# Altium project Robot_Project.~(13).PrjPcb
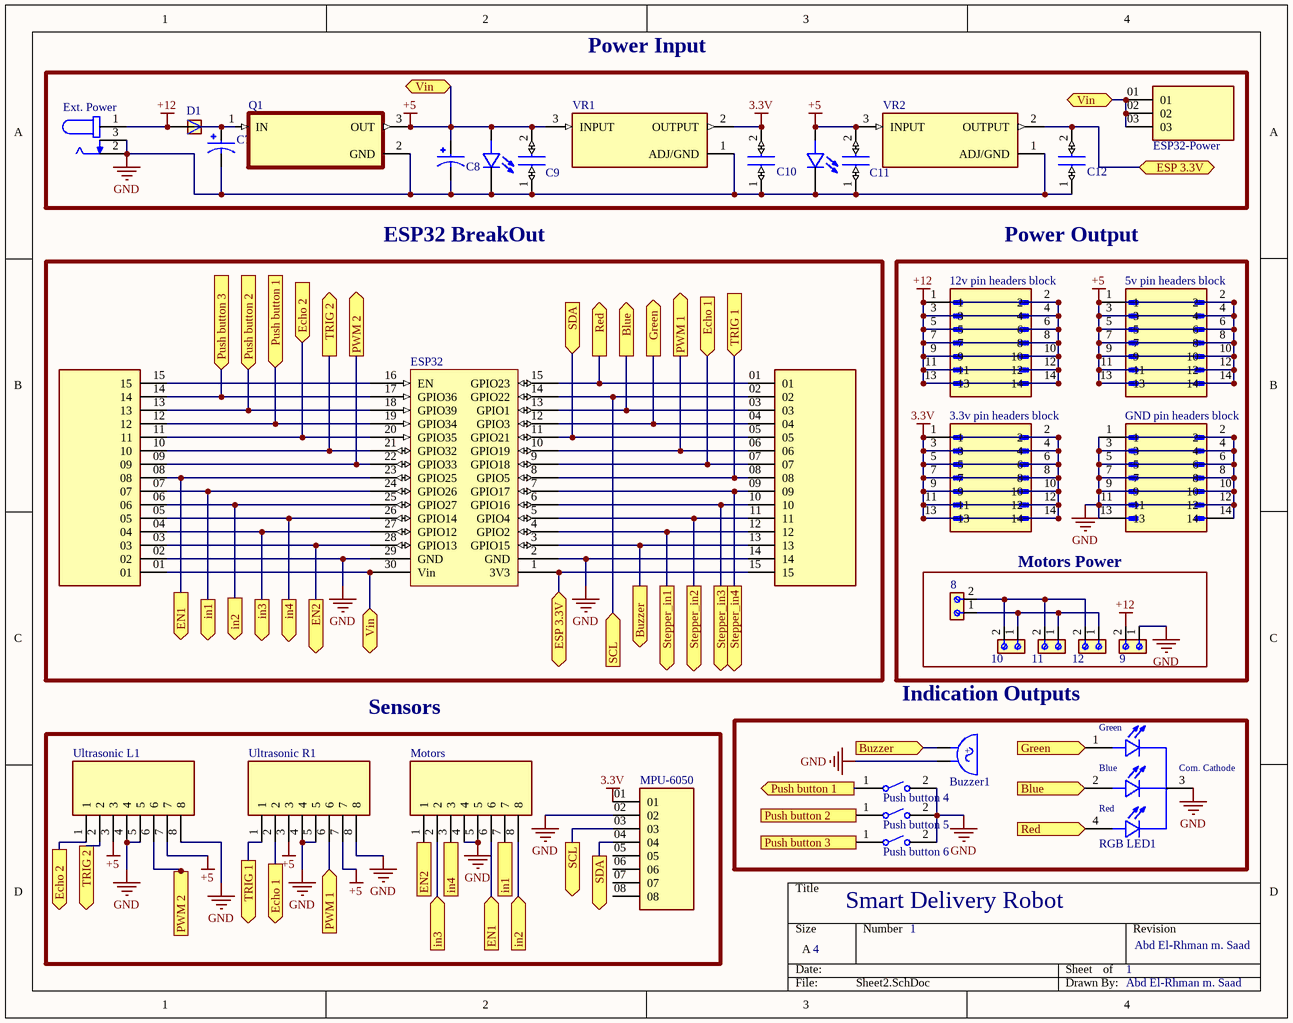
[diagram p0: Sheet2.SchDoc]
1 sheet, 35 parts. Net scope: flat (ports and power ports of the same name join across sheets).
Board files: PCB1.PcbDoc, PCB2.PcbDoc

## Sheet Sheet2.SchDoc: Smart Delivery Robot
size A; Date: 27/12/2023; DrawnBy: Abd El-Rhman m. Saad; Engineer: Abd El-Rhman m. Saad; SheetNumber: 2; SheetTotal: 2

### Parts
1  LED 5mm  [LED 5mm]  (value not drawn)
2  LED 5mm  [LED 5mm]  (value not drawn)
3.3v_pin_headers_block  3.3v pin headers block  [AMPHENOL_52601-S14-4LF]  (value not drawn)
5v_pin_headers_block  5v pin headers block  [AMPHENOL_52601-S14-4LF]  (value not drawn)
8  From Buck  [691213510002]  (value not drawn)
9  From Buck  [691213510002]  (value not drawn)
10  From Buck  [691213510002]  (value not drawn)
11  From Buck  [691213510002]  (value not drawn)
12  From Buck  [691213510002]  (value not drawn)
12v_pin_headers_block  12v pin headers block  [AMPHENOL_52601-S14-4LF]  (value not drawn)
Buzzer1  Buzzer  [Buzzer 5V]  (value not drawn)
C7  CAP  33UF 50V RADIAL  [CAP  33UF 50V RADIAL]  (value not drawn)
C8  CAP  33UF 50V RADIAL  [CAP  33UF 50V RADIAL]  (value not drawn)
C9  Ceramic Capacitor 100nF  [C320C]  (value not drawn)
C10  Ceramic Capacitor 100nF  [C320C]  (value not drawn)
C11  Ceramic Capacitor 100nF  [C320C]  (value not drawn)
C12  Ceramic Capacitor 100nF  [C320C]  (value not drawn)
D1  RL207  [DIOAD1300W80L670D310]  (value not drawn)
ESP32  ESP32DEVKITV1  [ESP32DEVKITV1]  (value not drawn)
ESP32-Power  TS-103-T-A-1  [SAMTEC_TS-103-T-A-1]  (value not drawn)
Ext._Power  DC Power Jack Female Socket  [DC Power Jack Female Socket]  (value not drawn)
GND_pin_headers_block  GND pin headers block  [AMPHENOL_52601-S14-4LF]  (value not drawn)
J1  TS-115-T-A-1  [SAMTEC_TS-115-T-A-1]  (value not drawn)
J2  TS-115-T-A-1  [SAMTEC_TS-115-T-A-1]  (value not drawn)
Motors  Pin header female block 8 pin  [Pin header female block 8 pin]  (value not drawn)
MPU-6050  MPU-6050  [MPU-6050]  (value not drawn)
Push_button_4  FSM8JRT  [TE_FSM8JRT]  (value not drawn)
Push_button_5  FSM8JRT  [TE_FSM8JRT]  (value not drawn)
Push_button_6  FSM8JRT  [TE_FSM8JRT]  (value not drawn)
Q1  LM7805CT  [TO254P1054X470X1955-3]  (value not drawn)
RGB_LED1  common cathode  [LED RGB 5mm]  (value not drawn)
Ultrasonic_L1  Pin header female block 8 pin  [Pin header female block 8 pin]  (value not drawn)
Ultrasonic_R1  Pin header female block 8 pin  [Pin header female block 8 pin]  (value not drawn)
VR1  LM1117T-3.3  [TO254P1054X470X1955-3]  (value not drawn)
VR2  LM1117T-3.3  [TO254P1054X470X1955-3]  (value not drawn)

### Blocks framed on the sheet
Power Input: 1 2 C7-C12 D1 ESP32-Power Ext._Power Q1 VR1 VR2
ESP32 BreakOut: ESP32 J1 J2
Power Output: 3.3v_pin_headers_block 5v_pin_headers_block 12v_pin_headers_block GND_pin_headers_block
Motors Power: 8-12
Indication Outputs: Buzzer1 Push_button_4-Push_button_6 RGB_LED1
Sensors: Motors MPU-6050 Ultrasonic_L1 Ultrasonic_R1

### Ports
Blue (in, see Sheet1[2B], Sheet1[4B], Sheet2[2B]), Blue (out, see Sheet1[2B], Sheet1[4B], Sheet2[4D]), Buzzer (in, see Sheet1[2C], Sheet1[4A], Sheet2[2C]), Buzzer (out, see Sheet1[2C], Sheet1[4A], Sheet2[3C]), Echo 1 (in, see Sheet1[3B], Sheet1[4B], Sheet2[1D]), Echo 1 (out, see Sheet1[3B], Sheet1[4B], Sheet2[3B]), Echo 2 (in, see Sheet1[1B], Sheet1[3B], Sheet2[1D]), Echo 2 (out, see Sheet1[1B], Sheet1[3B], Sheet2[1B]), EN1 (in, see Sheet1[1C], Sheet1[4C], Sheet2[1C]), EN1 (out, see Sheet1[1C], Sheet1[4C], Sheet2[2D]), EN2 (in, see Sheet1[2C], Sheet1[4C], Sheet2[1C]), EN2 (out, see Sheet1[2C], Sheet1[4C], Sheet2[2D]), ESP 3.3V (bidir, see Sheet1[2C], Sheet1[3A], Sheet2[2C]), ESP 3.3V (bidir, see Sheet1[2C], Sheet1[3A], Sheet2[4A]), Green (in, see Sheet1[3B], Sheet1[4B], Sheet2[3B]), Green (out, see Sheet1[3B], Sheet1[4B], Sheet2[4C]), in1 (in, see Sheet1[1C], Sheet1[4C], Sheet2[1C]), in1 (out, see Sheet1[1C], Sheet1[4C], Sheet2[2D]), in2 (in, see Sheet1[1C], Sheet1[4C], Sheet2[1C]), in2 (out, see Sheet1[1C], Sheet1[4C], Sheet2[2D]), in3 (in, see Sheet1[1C], Sheet1[4C], Sheet2[1C]), in3 (out, see Sheet1[1C], Sheet1[4C], Sheet2[2D]), in4 (in, see Sheet1[1C], Sheet1[4C], Sheet2[1C]), in4 (out, see Sheet1[1C], Sheet1[4C], Sheet2[2D]), Push button 1 (in, see Sheet1[1B], Sheet1[4C], Sheet2[3D]), Push button 1 (out, see Sheet1[1B], Sheet1[4C], Sheet2[1B]), Push button 2 (in, see Sheet1[1B], Sheet1[4D], Sheet2[3D]), Push button 2 (out, see Sheet1[1B], Sheet1[4D], Sheet2[1B]), Push button 3 (in, see Sheet1[1B], Sheet1[4D], Sheet2[3D]), Push button 3 (out, see Sheet1[1B], Sheet1[4D], Sheet2[1B]), PWM 1 (in, see Sheet1[3B], Sheet1[4B], Sheet2[3B]), PWM 1 (out, see Sheet1[3B], Sheet1[4B], Sheet2[2D]), PWM 2 (in, see Sheet1[2B], Sheet1[4B], Sheet2[2B]), PWM 2 (out, see Sheet1[2B], Sheet1[4B], Sheet2[1D]), Red (in, see Sheet1[2B], Sheet1[4B], Sheet2[2B]), Red (out, see Sheet1[2B], Sheet1[4B], Sheet2[4D]), SCL (in, see Sheet1[2C], Sheet1[3C], Sheet2[2D]), SCL (out, see Sheet1[2C], Sheet1[3C], Sheet2[2C]), SDA (in, see Sheet1[2B], Sheet1[4C], Sheet2[2D]), SDA (out, see Sheet1[2B], Sheet1[4C], Sheet2[2B]), Stepper_in1 (out, see Sheet1[2C]), Stepper_in2 (out, see Sheet1[3C]), Stepper_in3 (out, see Sheet1[3C]), Stepper_in4 (out, see Sheet1[3C]), TRIG 1 (in, see Sheet1[3B], Sheet1[4B], Sheet2[1D]), TRIG 1 (out, see Sheet1[3B], Sheet1[4B], Sheet2[3B]), TRIG 2 (out, see Sheet1[1B], Sheet1[3B], Sheet2[1D]), TRIG 2 (out, see Sheet1[1B], Sheet1[3B], Sheet2[2B]), Vin (bidir, see Sheet1[2A], Sheet1[2C], Sheet2[2A], Sheet2[2C]), Vin (bidir, see Sheet1[2A], Sheet1[2C], Sheet2[2A], Sheet2[4A]), Vin (bidir, see Sheet1[2A], Sheet1[2C], Sheet2[2C], Sheet2[4A])

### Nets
3.3V: 3.3v_pin_headers_block.1 3.3v_pin_headers_block.2 3.3v_pin_headers_block.3 3.3v_pin_headers_block.4 3.3v_pin_headers_block.5 3.3v_pin_headers_block.6 3.3v_pin_headers_block.7 3.3v_pin_headers_block.8 3.3v_pin_headers_block.9 3.3v_pin_headers_block.10 3.3v_pin_headers_block.11 3.3v_pin_headers_block.12 3.3v_pin_headers_block.13 3.3v_pin_headers_block.14 C10.2 MPU-6050.01 VR1.2(OUTPUT)
+5: 1.A 2.A 5v_pin_headers_block.1 5v_pin_headers_block.2 5v_pin_headers_block.3 5v_pin_headers_block.4 5v_pin_headers_block.5 5v_pin_headers_block.6 5v_pin_headers_block.7 5v_pin_headers_block.8 5v_pin_headers_block.9 5v_pin_headers_block.10 5v_pin_headers_block.11 5v_pin_headers_block.12 5v_pin_headers_block.13 5v_pin_headers_block.14 C8.P C9.2 C11.2 ESP32.30(Vin) ESP32-Power.01 ESP32-Power.02 ESP32-Power.03 J2.01 Q1.3(OUT) Ultrasonic_L1.3 Ultrasonic_L1.7 Ultrasonic_R1.3 Ultrasonic_R1.7 VR1.3(INPUT) VR2.3(INPUT) ; port Vin
+12: 9.2 12v_pin_headers_block.1 12v_pin_headers_block.2 12v_pin_headers_block.3 12v_pin_headers_block.4 12v_pin_headers_block.5 12v_pin_headers_block.6 12v_pin_headers_block.7 12v_pin_headers_block.8 12v_pin_headers_block.9 12v_pin_headers_block.10 12v_pin_headers_block.11 12v_pin_headers_block.12 12v_pin_headers_block.13 12v_pin_headers_block.14 D1.A Ext._Power.1
GND: 1.C 2.C 9.1 Buzzer1.NEG C7.N C8.N C9.1 C10.1 C11.1 C12.1 ESP32.2(GND) ESP32.29(GND) Ext._Power.2 Ext._Power.3 GND_pin_headers_block.1 GND_pin_headers_block.2 GND_pin_headers_block.3 GND_pin_headers_block.4 GND_pin_headers_block.5 GND_pin_headers_block.6 GND_pin_headers_block.7 GND_pin_headers_block.8 GND_pin_headers_block.9 GND_pin_headers_block.10 GND_pin_headers_block.11 GND_pin_headers_block.12 GND_pin_headers_block.13 GND_pin_headers_block.14 J1.14 J2.02 Motors.4 Motors.5 MPU-6050.02 Push_button_4.2 Push_button_5.2 Push_button_6.2 Q1.2(GND) RGB_LED1.3(Com._Cathode) Ultrasonic_L1.4 Ultrasonic_L1.5 Ultrasonic_L1.8 Ultrasonic_R1.4 Ultrasonic_R1.5 Ultrasonic_R1.8 VR1.1(ADJ/GND) VR2.1(ADJ/GND)
Net8_1: 8.1 10.1 11.1 12.1
Net8_2: 8.2 10.2 11.2 12.2
NetBuzzer1_POS: Buzzer1.POS ESP32.3(GPIO15) J1.13 ; port Buzzer
NetC7_P: C7.P D1.C Q1.1(IN)
NetC12_2: C12.2 ESP32.1(3V3) J1.15 VR2.2(OUTPUT) ; port ESP 3.3V
NetESP32_4: ESP32.4(GPIO2) J1.12 ; port Stepper_in1
NetESP32_5: ESP32.5(GPIO4) J1.11 ; port Stepper_in2
NetESP32_6: ESP32.6(GPIO16) J1.10 ; port Stepper_in3
NetESP32_7: ESP32.7(GPIO17) J1.09 ; port Stepper_in4
NetESP32_8: ESP32.8(GPIO5) J1.08 Ultrasonic_R1.1 ; port TRIG 1
NetESP32_9: ESP32.9(GPIO18) J1.07 Ultrasonic_R1.2 ; port Echo 1
NetESP32_10: ESP32.10(GPIO19) J1.06 Ultrasonic_R1.6 ; port PWM 1
NetESP32_11: ESP32.11(GPIO21) J1.05 MPU-6050.04 ; port SDA
NetESP32_12: ESP32.12(GPIO3) J1.04 RGB_LED1.1(Green) ; port Green
NetESP32_13: ESP32.13(GPIO1) J1.03 RGB_LED1.2(BLUE) ; port Blue
NetESP32_14: ESP32.14(GPIO22) J1.02 MPU-6050.03 ; port SCL
NetESP32_15: ESP32.15(GPIO23) J1.01 RGB_LED1.4(Red) ; port Red
NetESP32_16: ESP32.16(EN) J2.15
NetESP32_17: ESP32.17(GPIO36) J2.14 Push_button_6.1 ; port Push button 3
NetESP32_18: ESP32.18(GPIO39) J2.13 Push_button_5.1 ; port Push button 2
NetESP32_19: ESP32.19(GPIO34) J2.12 Push_button_4.1 ; port Push button 1
NetESP32_20: ESP32.20(GPIO35) J2.11 Ultrasonic_L1.1 ; port Echo 2
NetESP32_21: ESP32.21(GPIO32) J2.10 Ultrasonic_L1.2 ; port TRIG 2
NetESP32_22: ESP32.22(GPIO33) J2.09 Ultrasonic_L1.6 ; port PWM 2
NetESP32_23: ESP32.23(GPIO25) J2.08 Motors.6 ; port EN1
NetESP32_24: ESP32.24(GPIO26) J2.07 Motors.7 ; port in1
NetESP32_25: ESP32.25(GPIO27) J2.06 Motors.8 ; port in2
NetESP32_26: ESP32.26(GPIO14) J2.05 Motors.3 ; port in4
NetESP32_27: ESP32.27(GPIO12) J2.04 Motors.2 ; port in3
NetESP32_28: ESP32.28(GPIO13) J2.03 Motors.1 ; port EN2

Not connected (* = marked no-connect by the designer): MPU-6050 05 06 07 08

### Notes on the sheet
- 4
- 1

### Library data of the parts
1 2 = LED 5mm: Red 623nm LED Indication - Discrete 1.9V Radial; MF: {'manufacturer': u'Wurth Elektronik'}; MP: 151054RS03000
3.3v_pin_headers_block 5v_pin_headers_block 12v_pin_headers_block GND_pin_headers_block = 52601-S14-4LF: MF: {'manufacturer': u'Amphenol ICC (FCI)'}
8-12 = Terminal Block: 2 Position Wire to Board Terminal Block Horizontal with Board 0.200 (5.08mm) Through Hole; MF: Wurth Electronics
Buzzer1 = Buzzer 5V: BUZZER 2.3KHZ 4-6VDC; MF: {'manufacturer': u'Soberton Inc.'}; MP: WST-1205S
C7 C8 = CAP  33UF 50V RADIAL: NHG-A; MF: {'manufacturer': u'Panasonic'}; MP: ECA1HHG330I
C9-C12 = Ceramic Capacitor 100nF: 0.1ÂµF Â±20% 50V Ceramic Capacitor Z5U Radial; MF: KEMET; MP: C320C104M5U5TA
D1 = RL207: Semiconductors and Actives, Power Diodes, Discretes (diodes, transistors, thyristors ...), Diodes; MF: {'manufacturer': u'Diodes Inc.'}
ESP32-Power = TS-103-T-A-1: MF: {'manufacturer': u'Samtec'}
Ext._Power = DC Power Jack Female Socket: 2.0 mm Center Pin, 2.5 A, Right Angle, Through Hole, Dc Power Jack Connector; MF: {'manufacturer': u'CUI Devices'}; MP: PJ-002A
J1 J2 = TS-115-T-A-1: MF: {'manufacturer': u'Samtec'}
Motors Ultrasonic_L1 Ultrasonic_R1 = Pin header female block 8 pin: MF: {'manufacturer': u'TE Connectivity'}; MP: 5-534998-4
Push_button_4-Push_button_6 = FSM8JRT: Tactile Switches PUSHBUTTON SWITCH TACT; MF: {'manufacturer': u'TE Connectivity'}
Q1 = LM7805CT/NOPB: MF: {'manufacturer': u'Texas Instruments'}
RGB_LED1 = LED RGB 5mm: MF: {'manufacturer': u'Kingbright'}; MP: WP154A4SUREQBFZGC
VR1 VR2 = LM1117T-3.3/NOPB: MF: {'manufacturer': u'Texas Instruments'}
